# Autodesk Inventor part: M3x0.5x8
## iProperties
Company: 한국ATC센터
Created: 2009-02
Part Number: M3x0.5x8
Document SubType Name: Modeling
Designer: KYOUNG IL JANG
Density: 2.71 g/cm^3
Material: 알루미늄-6061
Vendor: CBT Solutions
Author: KYOUNG IL JANG
